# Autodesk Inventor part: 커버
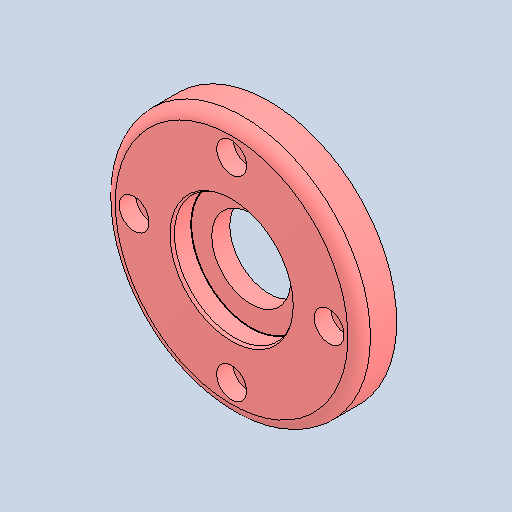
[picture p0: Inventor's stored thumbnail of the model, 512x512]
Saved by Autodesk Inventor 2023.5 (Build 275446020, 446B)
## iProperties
Created: 2026-07
Part Number: 커버
Material: 알루미늄 6061
Document SubType Name: Modeling
Designer: 1강의실14
Density: 2.71 g/cm^3
Appearance: 기본값
Author: jhkim
Sending System: Autodesk Inventor 2027
Preprocessor: ST-DEVELOPER v20.1
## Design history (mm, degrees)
node "커버1"
node "솔리드2"
node "솔리드1"
